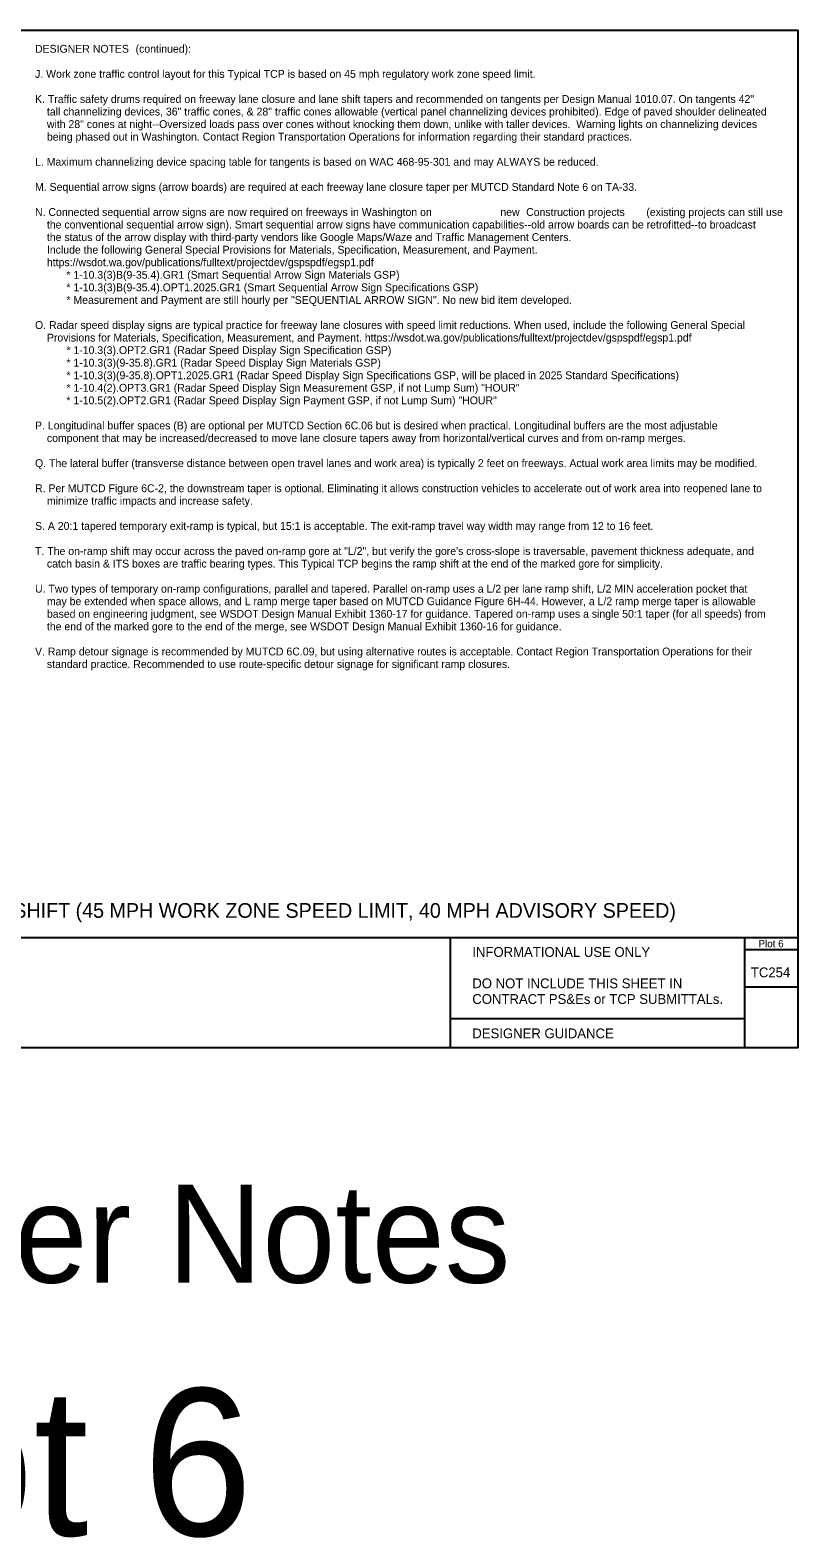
# Model space of a CAD drawing. Extents: x 99999 to 100116, y 99995 to 100013.
# Drawn here: x 100107.93 to 100115.75, y 99995.01 to 100010.37 of the extents above; entities that cross this region are included whole.
import ezdxf

# ---------------------------------------------------------------- set-up
doc = ezdxf.new("R2010")
doc.units = 0
for name, color, linetype in [('SH_DE_DetailHeading1Text', 7, 'Continuous'), ('SH_GI_GeneralNotesBodyText', 7, 'Continuous'), ('SH_GI_SheetLocationText', 7, 'Continuous'), ('SH_GI_TitleBlockText', 7, 'Continuous'), ('TR_WZ_WorkZoneDetails', 7, 'Continuous')]:
    doc.layers.add(name, color=color, linetype=linetype)

msp = doc.modelspace()

# ---------------------------------------------------------------- linework, layer by layer
at = {"layer": 'TR_WZ_WorkZoneDetails'}
for p, q in [((100100, 100001.126), (100115.75, 100001.126)), ((100112.205, 100001.126), (100112.205, 100000)), ((100115.208, 100000.295), (100112.205, 100000.295))]:
    msp.add_line(p, q, dxfattribs=at)
msp.add_lwpolyline([(100100, 100010.375), (100115.75, 100010.375), (100115.75, 100000), (100100, 100000)], close=True, dxfattribs=at)
for points in [[(100115.208, 100001.126), (100115.208, 100000)], [(100115.75, 100001.001), (100115.208, 100001.001)], [(100115.75, 100000.618), (100115.208, 100000.618)]]:
    msp.add_lwpolyline(points, dxfattribs=at)

# ---------------------------------------------------------------- texts
at = {"layer": 'SH_DE_DetailHeading1Text'}
msp.add_text("FREEWAY (2 LANES): SINGLE LEFT LANE CLOSURE, 9' MAX RIGHT SHOULDER SHIFT (45 MPH WORK ZONE SPEED LIMIT, 40 MPH ADVISORY SPEED)", height=0.15, rotation=360, dxfattribs=at).set_placement((100100.091, 100001.326))
at = {"layer": 'SH_GI_GeneralNotesBodyText'}
for s, p in [('DESIGNER NOTES', (100107.975, 100010.145)), (' (continued):', (100108.97, 100010.145)), ('J. Work zone traffic control layout for this Typical TCP is based on 45 mph regulatory work zone speed limit.', (100107.975, 100009.889)), ('K. Traffic safety drums required on freeway lane closure and lane shift tapers and recommended on tangents per Design Manual 1010.07. On tangents 42" ', (100107.975, 100009.633)), ('tall channelizing devices, 36" traffic cones, & 28" traffic cones allowable (vertical panel channelizing devices prohibited). Edge of paved shoulder delineated ', (100108.096, 100009.505)), ('with 28" cones at night--Oversized loads pass over cones without knocking them down, unlike with taller devices.  Warning lights on channelizing devices ', (100108.096, 100009.377)), ('being phased out in Washington. Contact Region Transportation Operations for information regarding their standard practices.', (100108.096, 100009.249)), ('L. Maximum channelizing device spacing table for tangents is based on WAC 468-95-301 and may ALWAYS be reduced.', (100107.975, 100008.993)), ('M. Sequential arrow signs (arrow boards) are required at each freeway lane closure taper per MUTCD Standard Note 6 on TA-33.', (100107.975, 100008.737)), ('N. Connected sequential arrow signs are now required on freeways in Washington on ', (100107.975, 100008.481)), (' Construction projects ', (100112.951, 100008.481)), ('(existing projects can still use ', (100114.206, 100008.481)), ('the conventional sequential arrow sign). Smart sequential arrow signs have communication capabilities--old arrow boards can be retrofitted--to broadcast ', (100108.096, 100008.353)), ('new', (100112.718, 100008.481)), ('the status of the arrow display with third-party vendors like Google Maps/Waze and Traffic Management Centers.', (100108.096, 100008.225)), ('Include the following General Special Provisions for Materials, Specification, Measurement, and Payment. ', (100108.096, 100008.097)), ('https://wsdot.wa.gov/publications/fulltext/projectdev/gspspdf/egsp1.pdf', (100108.096, 100007.969)), ('* 1-10.3(3)B(9-35.4).GR1 (Smart Sequential Arrow Sign Materials GSP)', (100108.295, 100007.841)), ('* 1-10.3(3)B(9-35.4).OPT1.2025.GR1 (Smart Sequential Arrow Sign Specifications GSP)', (100108.295, 100007.713)), ('* Measurement and Payment are still hourly per "SEQUENTIAL ARROW SIGN". No new bid item developed.', (100108.295, 100007.585)), ('O. Radar speed display signs are typical practice for freeway lane closures with speed limit reductions. When used, include the following General Special ', (100107.975, 100007.329)), ('Provisions for Materials, Specification, Measurement, and Payment. https://wsdot.wa.gov/publications/fulltext/projectdev/gspspdf/egsp1.pdf', (100108.096, 100007.201)), ('* 1-10.3(3).OPT2.GR1 (Radar Speed Display Sign Specification GSP)', (100108.295, 100007.073)), ('* 1-10.3(3)(9-35.8).GR1 (Radar Speed Display Sign Materials GSP)', (100108.295, 100006.945)), ('* 1-10.3(3)(9-35.8).OPT1.2025.GR1 (Radar Speed Display Sign Specifications GSP, will be placed in 2025 Standard Specifications)', (100108.295, 100006.817)), ('* 1-10.4(2).OPT3.GR1 (Radar Speed Display Sign Measurement GSP, if not Lump Sum) "HOUR"', (100108.295, 100006.689)), ('* 1-10.5(2).OPT2.GR1 (Radar Speed Display Sign Payment GSP, if not Lump Sum) "HOUR"', (100108.295, 100006.561)), ('P. Longitudinal buffer spaces (B) are optional per MUTCD Section 6C.06 but is desired when practical. Longitudinal buffers are the most adjustable ', (100107.975, 100006.305)), ('component that may be increased/decreased to move lane closure tapers away from horizontal/vertical curves and from on-ramp merges.', (100108.096, 100006.177)), ('Q. The lateral buffer (transverse distance between open travel lanes and work area) is typically 2 feet on freeways. Actual work area limits may be modified.', (100107.975, 100005.921)), ('R. Per MUTCD Figure 6C-2, the downstream taper is optional. Eliminating it allows construction vehicles to accelerate out of work area into reopened lane to ', (100107.975, 100005.665)), ('minimize traffic impacts and increase safety.', (100108.096, 100005.537)), ('S. A 20:1 tapered temporary exit-ramp is typical, but 15:1 is acceptable. The exit-ramp travel way width may range from 12 to 16 feet.', (100107.975, 100005.281)), ('T. The on-ramp shift may occur across the paved on-ramp gore at "L/2", but verify the gore\'s cross-slope is traversable, pavement thickness adequate, and ', (100107.975, 100005.025)), ('catch basin & ITS boxes are traffic bearing types. This Typical TCP begins the ramp shift at the end of the marked gore for simplicity.', (100108.096, 100004.897)), ('U. Two types of temporary on-ramp configurations, parallel and tapered. Parallel on-ramp uses a L/2 per lane ramp shift, L/2 MIN acceleration pocket that ', (100107.975, 100004.641)), ('may be extended when space allows, and L ramp merge taper based on MUTCD Guidance Figure 6H-44. However, a L/2 ramp merge taper is allowable ', (100108.096, 100004.513)), ('based on engineering judgment, see WSDOT Design Manual Exhibit 1360-17 for guidance. Tapered on-ramp uses a single 50:1 taper (for all speeds) from ', (100108.096, 100004.385)), ('the end of the marked gore to the end of the merge, see WSDOT Design Manual Exhibit 1360-16 for guidance.', (100108.096, 100004.257)), ('V. Ramp detour signage is recommended by MUTCD 6C.09, but using alternative routes is acceptable. Contact Region Transportation Operations for their ', (100107.975, 100004.001)), ('standard practice. Recommended to use route-specific detour signage for significant ramp closures.', (100108.096, 100003.873))]:
    msp.add_text(s, height=0.08, rotation=360, dxfattribs=at).set_placement(p)
at = {"layer": 'SH_GI_SheetLocationText'}
for s, height, p in [('Plot 6', 0.075, (100115.349, 100001.025)), ('Designer Notes', 1, (100103.603, 99997.607)), ('Plot 6', 1.5, (100105.062, 99995.027))]:
    msp.add_text(s, height=height, dxfattribs=at).set_placement(p)
at = {"layer": 'SH_GI_TitleBlockText'}
msp.add_text('TC254', height=0.1, dxfattribs=at).set_placement((100115.271, 100000.72))
at = {"layer": 'TR_WZ_WorkZoneDetails'}
for s, p in [('INFORMATIONAL USE ONLY', (100112.432, 100000.928)), ('DO NOT INCLUDE THIS SHEET IN', (100112.432, 100000.608)), ('CONTRACT PS&Es or TCP SUBMITTALs.', (100112.432, 100000.448)), ('DESIGNER GUIDANCE', (100112.432, 100000.098))]:
    msp.add_text(s, height=0.1, dxfattribs=at).set_placement(p)

doc.saveas('drawing.dxf')
